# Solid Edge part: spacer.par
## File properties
Author: Binay
Template: sync ansi part.par
Last saved by: Cadcim
Revision: 3
Application: Solid Edge
Accuracy: 0.990
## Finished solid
Body 1: solid body, 4 faces, 4 edges, 0 vertices.
  Faces by surface: cylinder 2, plane 2
  Edges by curve: circle 4
Bounding box of the edges (mm): 31.750 x 31.750 x 34.925, from (-23.8946, 129.8949, -17.4625) to (7.8554, 161.6449, 17.4625).
Cylindrical faces by radius (mm): R12.7 x1, R15.875 x1
Planar faces by outward normal: +z 1, -z 1
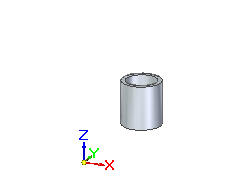
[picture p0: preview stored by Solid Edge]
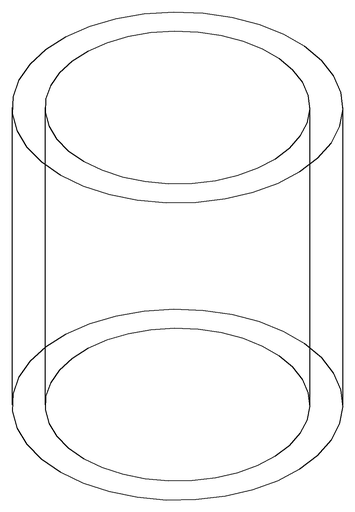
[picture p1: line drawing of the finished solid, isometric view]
